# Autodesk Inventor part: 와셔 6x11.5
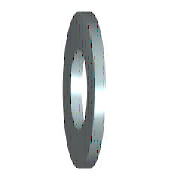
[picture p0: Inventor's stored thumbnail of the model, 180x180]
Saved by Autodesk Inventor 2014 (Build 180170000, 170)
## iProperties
IsCustomPart: 1
Created: 2012-02
Part Number: 와셔 6x11.5
Material: 강철, 연강
Description: 평면 와셔
Document SubType Name: Modeling
Standard: KS B 1326
Designer: mduedu
Standards Organization: KS
Language: ko-KR
Size Designation: 6x11.5
Categories: <MemberInstance><Categories><Category DisplayName="조임쇠" InternalName="e4da775c-781d-43d5-af7c-5136215cf5a6" Mnemonic="FSTN"><Category DisplayName="와셔" InternalN
Density: 1 g/cm^3
Appearance: Pink
Author: mduedu
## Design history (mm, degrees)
sketch "스케치"
  geometry: C1 r 5.75 at (0, 0); C2 r 3.2 at (0, 0); 1 further point
  constraints: 2 centre point, 2 coincident
  dimensions: "d0" = 6.4 diameter of C2 (= SD1); "d1" = 11.5 diameter of C1 (= SD2)
extrude "본체" new body sketch "스케치" distance "d2" = 1.6 (= SD); taper "d3" = 0 deg
workaxis "Work Axis1"
workplane "Work Plane1"
body "Solid1"
other parameters: "SD1" = 6.4 [user parameter; used in 1 equation term], "SD2" = 11.5 [user parameter; used in 1 equation term], "SD" = 1.6 [user parameter; used in 1 equation term], "d4" = 0, "d5" = 0, "d6" = 0, "d7" = 0, "NND" = 6 [user parameter]
